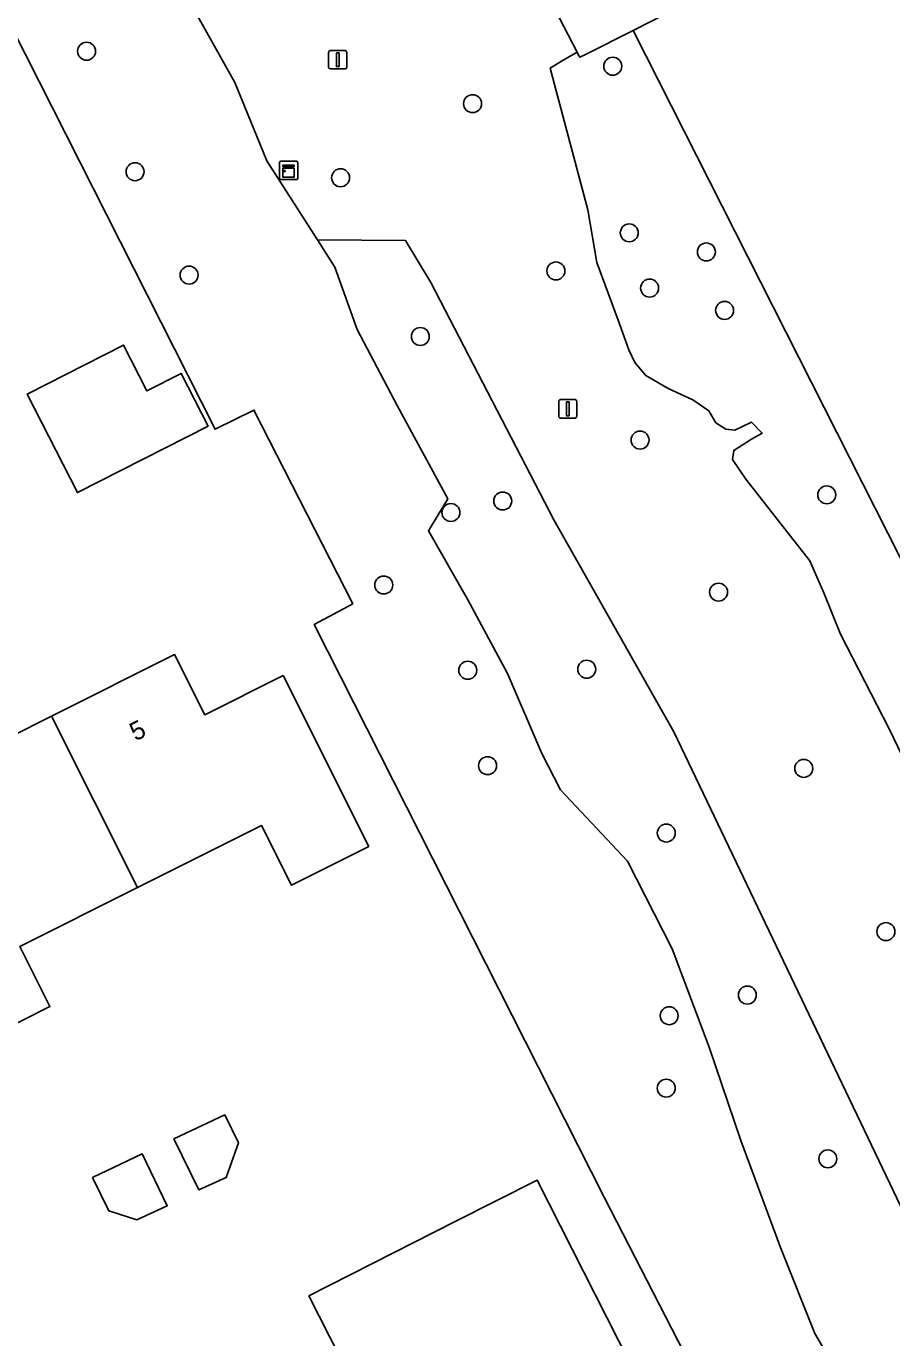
# Model space of a CAD drawing. Extents: x 162722 to 165104, y 384719 to 386284.
# Drawn here: x 163805.7 to 163852.8, y 384930.1 to 385001.5 of the extents above; entities that cross this region are included whole.
import ezdxf

# ---------------------------------------------------------------- set-up
doc = ezdxf.new("R2010")
doc.units = 0
for name, color, linetype in [('IMGEO_Boom', 7, 'Continuous'), ('IMGEO_Erf', 7, 'Continuous'), ('IMGEO_Groenvoorziening', 7, 'Continuous'), ('IMGEO_Kast', 7, 'Continuous'), ('IMGEO_Lichtmast', 7, 'Continuous'), ('IMGEO_Pand', 7, 'Continuous'), ('IMGEO_Pand_nummerreeks', 7, 'Continuous'), ('IMGEO_Parkeervlak_open', 7, 'Continuous')]:
    doc.layers.add(name, color=color, linetype=linetype)

msp = doc.modelspace()

# ---------------------------------------------------------------- linework, layer by layer
at = {"layer": 'IMGEO_Boom'}
for centre in [(163808.943, 385000.17), (163837.578, 384999.354), (163829.948, 384997.314), (163811.579, 384993.61), (163822.768, 384993.282), (163838.477, 384990.281), (163842.671, 384989.241), (163814.52, 384987.979), (163834.484, 384988.206), (163839.585, 384987.274), (163843.665, 384986.056), (163827.106, 384984.637), (163839.062, 384978.997), (163849.225, 384976.016), (163828.769, 384975.054), (163831.589, 384975.681), (163825.114, 384971.108), (163843.337, 384970.719), (163829.686, 384966.466), (163836.159, 384966.523), (163830.765, 384961.27), (163847.971, 384961.124), (163840.491, 384957.602), (163852.442, 384952.235), (163844.901, 384948.78), (163840.648, 384947.657), (163840.49, 384943.712), (163849.282, 384939.865)]:
    msp.add_circle(centre, 0.489, dxfattribs=at)
at = {"layer": 'IMGEO_Erf'}
for points in [[(163883.755, 384994.016), (163880.721, 385000), (163880.397, 385000.638), (163874.468, 385012.289), (163872.821, 385015.517), (163871.523, 385018.049), (163838.691, 385001.291), (163859.479, 384960.25), (163871.364, 384937.05), (163900.699, 384951.83)], [(163834.666, 384918.562), (163844.43, 384923.507), (163837.132, 384937.732), (163821.324, 384968.955), (163823.424, 384970.076), (163818.047, 384980.633), (163815.938, 384979.592), (163810.019, 384991.283), (163805.625, 385000), (163802.343, 385006.509), (163792.25, 385001.396), (163789.58, 385000.245), (163789.311, 385000), (163781.701, 384993.056), (163774.901, 384986.825), (163774.567, 384986.495)], [(163821.046, 384932.405), (163829, 384936.444), (163833.458, 384938.708), (163838.531, 384928.718), (163835.054, 384926.953), (163835.259, 384926.552)], [(163833.216, 384925.514), (163833.011, 384925.915), (163826.118, 384922.415), (163823.854, 384926.874), (163821.046, 384932.405)]]:
    msp.add_lwpolyline(points, dxfattribs=at)
for points in [[(163805.711, 384981.5), (163810.954, 384984.172), (163812.226, 384981.676), (163814.096, 384982.629), (163815.557, 384979.762), (163808.444, 384976.137)], [(163802.697, 384946.019), (163800.298, 384950.802), (163798.056, 384955.271), (163802.004, 384957.251), (163800.325, 384960.599), (163807.029, 384963.961), (163813.731, 384967.323), (163815.378, 384964.04), (163819.633, 384966.174), (163824.299, 384956.872), (163820.089, 384954.76), (163818.453, 384958.02), (163811.707, 384954.636), (163805.306, 384951.425), (163806.948, 384948.151)], [(163813.697, 384940.949), (163816.468, 384942.256), (163817.205, 384940.742), (163816.542, 384938.857), (163815.045, 384938.169)], [(163809.26, 384938.856), (163811.968, 384940.134), (163813.337, 384937.309), (163811.672, 384936.543), (163810.147, 384937.027)]]:
    msp.add_lwpolyline(points, close=True, dxfattribs=at)
at = {"layer": 'IMGEO_Groenvoorziening'}
for points in [[(163798.727, 385048.566), (163805.421, 385035.138), (163808.847, 385028.154), (163809.035, 385026.84), (163808.566, 385025.713), (163807.026, 385024.596), (163805.95, 385023.625), (163804.115, 385022.684), (163799.657, 385020.033), (163800.305, 385018.786), (163803.653, 385020.249), (163804.532, 385019.055), (163810.006, 385008.789), (163813.545, 385004.677), (163817.003, 384998.463), (163818.75, 384994.205), (163821.467, 384989.96), (163821.501, 384989.907), (163826.306, 384989.862), (163827.686, 384987.569), (163834.379, 384974.661), (163840.9, 384963.114), (163856.826, 384929.784)], [(163850.721, 384926.692), (163848.58, 384930.349), (163846.709, 384935.032), (163844.556, 384940.861), (163842.832, 384945.951), (163840.819, 384951.291), (163838.385, 384956.066), (163834.732, 384959.963), (163833.717, 384961.939), (163831.854, 384966.281), (163829.673, 384970.329), (163827.544, 384974.063), (163828.596, 384975.798), (163825.844, 384980.889), (163823.674, 384985.023), (163822.453, 384988.419), (163821.501, 384989.907), (163821.467, 384989.96), (163818.75, 384994.205), (163817.003, 384998.463), (163813.545, 385004.677), (163810.006, 385008.789), (163804.532, 385019.055)], [(163853.801, 384960.834), (163852.627, 384963.273), (163849.971, 384968.432), (163849.064, 384970.673), (163848.309, 384972.427), (163844.815, 384976.864), (163844.093, 384977.94), (163844.164, 384978.438), (163845.121, 384979.042), (163845.711, 384979.375), (163845.12, 384979.978), (163844.217, 384979.53), (163843.733, 384979.601), (163843.192, 384979.942), (163842.802, 384980.583), (163841.944, 384981.184), (163840.599, 384981.814), (163839.383, 384982.509), (163838.772, 384983.214), (163838.454, 384983.914), (163837.877, 384985.52), (163836.71, 384988.663), (163836.22, 384991.538), (163834.165, 384999.249), (163834.784, 384999.632), (163835.644, 385000.113), (163834.679, 385001.975)], [(163859.479, 384960.25), (163838.691, 385001.291), (163836.088, 385000), (163835.779, 384999.853), (163835.703, 385000), (163835.644, 385000.113), (163834.784, 384999.632), (163834.165, 384999.249), (163836.22, 384991.538), (163836.71, 384988.663), (163837.877, 384985.52), (163838.454, 384983.914), (163838.772, 384983.214), (163839.383, 384982.509), (163840.599, 384981.814), (163841.944, 384981.184), (163842.802, 384980.583), (163843.192, 384979.942), (163843.733, 384979.601), (163844.217, 384979.53), (163845.12, 384979.978), (163845.711, 384979.375), (163845.121, 384979.042), (163844.164, 384978.438), (163844.093, 384977.94), (163844.815, 384976.864), (163848.309, 384972.427), (163849.064, 384970.673), (163849.971, 384968.432), (163852.627, 384963.273), (163853.801, 384960.834)], [(163805.625, 385000), (163810.019, 384991.283), (163815.938, 384979.592), (163818.047, 384980.633), (163823.424, 384970.076), (163821.324, 384968.955), (163837.132, 384937.732), (163844.43, 384923.507)]]:
    msp.add_lwpolyline(points, dxfattribs=at)
msp.add_lwpolyline([(163821.501, 384989.907), (163822.453, 384988.419), (163823.674, 384985.023), (163825.844, 384980.889), (163828.596, 384975.798), (163827.544, 384974.063), (163829.673, 384970.329), (163831.854, 384966.281), (163833.717, 384961.939), (163834.732, 384959.963), (163838.385, 384956.066), (163840.819, 384951.291), (163842.832, 384945.951), (163844.556, 384940.861), (163846.709, 384935.032), (163848.58, 384930.349), (163850.721, 384926.692), (163850.884, 384926.775), (163854.555, 384928.634), (163856.826, 384929.784), (163840.9, 384963.114), (163834.379, 384974.661), (163827.686, 384987.569), (163826.306, 384989.862)], close=True, dxfattribs=at)
at = {"layer": 'IMGEO_Kast'}
for p, q in [((163819.436, 384993.256), (163819.436, 384994.097)), ((163819.436, 384994.097), (163819.436, 384993.256)), ((163819.511, 384994.181), (163820.352, 384994.181)), ((163820.352, 384994.181), (163819.511, 384994.181)), ((163820.436, 384994.106), (163820.436, 384993.265)), ((163820.436, 384993.265), (163820.436, 384994.106)), ((163820.361, 384993.181), (163819.52, 384993.181)), ((163819.52, 384993.181), (163820.361, 384993.181))]:
    msp.add_line(p, q, dxfattribs=at)
for points in [[(163819.631, 384993.971), (163820.231, 384993.971), (163820.231, 384993.886), (163819.631, 384993.886), (163819.631, 384993.971)], [(163819.631, 384993.796), (163820.231, 384993.796), (163820.231, 384993.307), (163819.631, 384993.307), (163819.631, 384993.796)]]:
    msp.add_lwpolyline(points, dxfattribs=at)
msp.add_circle((163819.715, 384993.645), 0.0377, dxfattribs=at)
for centre, start, end in [((163819.514, 384994.103), 92.4484, 184.28452), ((163819.514, 384994.103), 92.4484, 184.28452), ((163820.358, 384994.103), 2.4484, 94.28452), ((163820.358, 384994.103), 2.4484, 94.28452), ((163819.514, 384993.259), 182.4484, 274.28452), ((163819.514, 384993.259), 182.4484, 274.28452), ((163820.358, 384993.259), 272.4484, 4.28452), ((163820.358, 384993.259), 272.4484, 4.28452)]:
    msp.add_arc(centre, 0.0779, start, end, dxfattribs=at)
at = {"layer": 'IMGEO_Lichtmast'}
for p, q in [((163822.117, 384999.305), (163822.117, 385000.105)), ((163822.117, 385000.105), (163822.117, 384999.305)), ((163822.217, 385000.205), (163823.007, 385000.205)), ((163823.007, 385000.205), (163822.217, 385000.205)), ((163823.107, 385000.105), (163823.107, 384999.305)), ((163823.107, 384999.305), (163823.107, 385000.105)), ((163823.007, 384999.205), (163822.217, 384999.205)), ((163822.217, 384999.205), (163823.007, 384999.205)), ((163834.734, 384981.199), (163835.524, 384981.199)), ((163835.524, 384981.199), (163834.734, 384981.199)), ((163834.634, 384980.299), (163834.634, 384981.099)), ((163834.634, 384981.099), (163834.634, 384980.299)), ((163835.624, 384981.099), (163835.624, 384980.299)), ((163835.624, 384980.299), (163835.624, 384981.099)), ((163835.524, 384980.199), (163834.734, 384980.199)), ((163834.734, 384980.199), (163835.524, 384980.199))]:
    msp.add_line(p, q, dxfattribs=at)
for points in [[(163822.537, 385000.08), (163822.687, 385000.08), (163822.687, 384999.33), (163822.537, 384999.33), (163822.537, 385000.08)], [(163835.054, 384981.074), (163835.204, 384981.074), (163835.204, 384980.324), (163835.054, 384980.324), (163835.054, 384981.074)]]:
    msp.add_lwpolyline(points, dxfattribs=at)
for centre, start, end in [((163822.217, 385000.105), 90, 180), ((163822.217, 385000.105), 90, 180), ((163823.007, 385000.105), 0, 90), ((163823.007, 385000.105), 360, 90), ((163822.217, 384999.305), 180, 270), ((163822.217, 384999.305), 180, 270), ((163823.007, 384999.305), 270, 0), ((163823.007, 384999.305), 270, 0), ((163834.734, 384981.099), 90, 180), ((163834.734, 384981.099), 90, 180), ((163835.524, 384981.099), 0, 90), ((163835.524, 384981.099), 360, 90), ((163834.734, 384980.299), 180, 270), ((163834.734, 384980.299), 180, 270), ((163835.524, 384980.299), 270, 0), ((163835.524, 384980.299), 270, 0)]:
    msp.add_arc(centre, 0.1, start, end, dxfattribs=at)
at = {"layer": 'IMGEO_Pand'}
for points in [[(163814.096, 384982.629), (163812.226, 384981.676), (163810.954, 384984.172), (163805.711, 384981.5), (163808.444, 384976.137), (163815.557, 384979.762)], [(163811.707, 384954.636), (163818.453, 384958.02), (163820.089, 384954.76), (163824.299, 384956.872), (163819.633, 384966.174), (163815.378, 384964.04), (163813.731, 384967.323), (163807.029, 384963.961)], [(163807.029, 384963.961), (163800.325, 384960.599), (163802.004, 384957.251), (163798.056, 384955.271), (163800.298, 384950.802), (163802.697, 384946.019), (163806.948, 384948.151), (163805.306, 384951.425), (163811.707, 384954.636)], [(163816.468, 384942.256), (163813.697, 384940.949), (163815.045, 384938.169), (163816.542, 384938.857), (163817.205, 384940.742)], [(163809.26, 384938.856), (163810.147, 384937.027), (163811.672, 384936.543), (163813.337, 384937.309), (163811.968, 384940.134)]]:
    msp.add_lwpolyline(points, close=True, dxfattribs=at)
msp.add_lwpolyline([(163835.259, 384926.552), (163835.054, 384926.953), (163838.531, 384928.718), (163833.458, 384938.708), (163829, 384936.444), (163821.046, 384932.405), (163823.854, 384926.874), (163826.118, 384922.415), (163833.011, 384925.915), (163833.216, 384925.514)], dxfattribs=at)
at = {"layer": 'IMGEO_Parkeervlak_open'}
msp.add_lwpolyline([(163871.523, 385018.049), (163870.157, 385020.662), (163876.358, 385023.81), (163878.883, 385025.088), (163886.115, 385028.743), (163884.686, 385031.448), (163866.282, 385022.121), (163845.497, 385011.535), (163833.069, 385005.08), (163833.567, 385004.119), (163834.679, 385001.975), (163835.644, 385000.113), (163835.703, 385000), (163835.779, 384999.853), (163836.088, 385000), (163838.691, 385001.291)], close=True, dxfattribs=at)

# ---------------------------------------------------------------- texts
at = {"layer": 'IMGEO_Pand_nummerreeks'}
msp.add_text('5', height=1, rotation=26.63681, dxfattribs=at).set_placement((163811.604, 384962.587))

doc.saveas('drawing.dxf')
